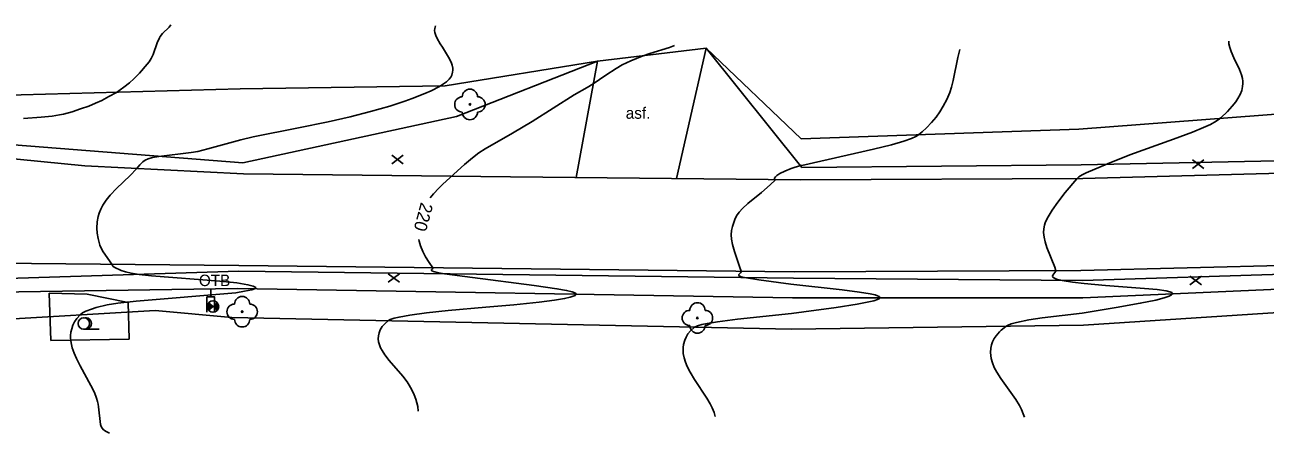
# Model space of a CAD drawing. Extents: x -593772 to -592667, y -1183541 to -1183371.
# Drawn here: x -593692.9 to -593611.5, y -1183405.1 to -1183378.3 of the extents above; entities that cross this region are included whole.
import ezdxf

# ---------------------------------------------------------------- set-up
doc = ezdxf.new("R2010")
doc.units = 0
for name, color, linetype in [('bez obruby', 7, 'Continuous'), ('hlavni vrstevnice', 7, 'Continuous'), ('popis ploch', 7, 'Continuous'), ('rozhrani ploch', 7, 'Continuous'), ('Statni bodove pole', 7, 'Continuous'), ('svisle dopravni znaceni', 7, 'Continuous'), ('terenni hrany', 7, 'Continuous'), ('vrstevnice', 7, 'Continuous'), ('zelen', 7, 'Continuous')]:
    doc.layers.add(name, color=color, linetype=linetype)

msp = doc.modelspace()

# ---------------------------------------------------------------- linework, layer by layer
at = {"layer": 'bez obruby'}
for p, q in [((-593688.93, -1183387.52), (-593695.87, -1183386.84)), ((-593678.52, -1183388.04), (-593688.93, -1183387.52)), ((-593605.56, -1183387.87), (-593623.44, -1183388.36)), ((-593660.99, -1183388.25), (-593678.52, -1183388.04)), ((-593641.96, -1183388.45), (-593660.99, -1183388.25)), ((-593623.44, -1183388.36), (-593641.96, -1183388.45)), ((-593678.82, -1183394.05), (-593694.9, -1183393.91)), ((-593642.38, -1183394.48), (-593678.82, -1183394.05)), ((-593623.56, -1183394.39), (-593642.38, -1183394.48)), ((-593605.48, -1183393.94), (-593623.56, -1183394.39))]:
    msp.add_line(p, q, dxfattribs=at)
at = {"layer": 'hlavni vrstevnice'}
for points in [[(-593650.242, -1183379.644), (-593650.564, -1183379.763), (-593651.862, -1183380.157), (-593652.355, -1183380.33), (-593653.108, -1183380.643), (-593653.661, -1183380.914), (-593654.072, -1183381.145), (-593654.742, -1183381.571), (-593655.581, -1183382.152), (-593655.956, -1183382.382), (-593656.811, -1183382.866), (-593659.585, -1183384.613), (-593660.862, -1183385.385), (-593662.658, -1183386.403), (-593663.076, -1183386.676), (-593663.493, -1183386.995), (-593664.016, -1183387.44), (-593665.438, -1183388.729), (-593665.71, -1183388.996), (-593666.058, -1183389.367), (-593666.277, -1183389.63)], [(-593667.008, -1183392.358), (-593666.988, -1183392.474), (-593666.899, -1183392.779), (-593666.753, -1183393.138), (-593666.568, -1183393.498), (-593666.345, -1183393.859), (-593666.097, -1183394.203), (-593666.09, -1183394.244), (-593666.128, -1183394.296), (-593666.183, -1183394.342), (-593666.198, -1183394.373), (-593666.171, -1183394.405), (-593666.051, -1183394.458), (-593665.733, -1183394.534), (-593665.336, -1183394.6), (-593663.482, -1183394.853), (-593659.452, -1183395.363), (-593657.951, -1183395.584), (-593657.316, -1183395.698), (-593656.943, -1183395.787), (-593656.77, -1183395.849), (-593656.701, -1183395.89), (-593656.68, -1183395.91), (-593656.675, -1183395.929), (-593656.68, -1183395.953), (-593656.747, -1183396.018), (-593656.881, -1183396.081), (-593657.073, -1183396.141), (-593657.45, -1183396.225), (-593658.11, -1183396.335), (-593659.108, -1183396.46), (-593660.779, -1183396.628), (-593662.608, -1183396.788), (-593665.08, -1183397.017), (-593666.516, -1183397.174), (-593667.594, -1183397.319), (-593668.306, -1183397.444), (-593668.636, -1183397.522), (-593668.898, -1183397.608), (-593669.011, -1183397.667), (-593669.227, -1183397.854), (-593669.411, -1183398.063), (-593669.541, -1183398.268), (-593669.624, -1183398.469), (-593669.668, -1183398.668), (-593669.676, -1183398.865), (-593669.653, -1183399.06), (-593669.601, -1183399.253), (-593669.525, -1183399.447), (-593669.427, -1183399.636), (-593669.248, -1183399.916), (-593668.961, -1183400.292), (-593668.068, -1183401.318), (-593667.778, -1183401.696), (-593667.711, -1183401.795), (-593667.49, -1183402.17), (-593667.311, -1183402.547), (-593667.204, -1183402.829), (-593667.137, -1183403.063), (-593667.088, -1183403.305), (-593667.057, -1183403.601)]]:
    msp.add_lwpolyline(points, dxfattribs=at)
at = {"layer": 'popis ploch'}
msp.add_line((-593689, -1183398.24), (-593688, -1183398.24), dxfattribs=at)
msp.add_circle((-593689, -1183397.866), 0.375, dxfattribs=at)
msp.add_arc((-593688.875, -1183397.866), 0.375, 260.40593, 99.59407, dxfattribs=at)
at = {"layer": 'rozhrani ploch'}
for p, q in [((-593655.28, -1183380.66), (-593648.15, -1183379.82)), ((-593648.15, -1183379.82), (-593650.103, -1183388.364)), ((-593656.687, -1183388.295), (-593655.28, -1183380.66))]:
    msp.add_line(p, q, dxfattribs=at)
at = {"layer": 'Statni bodove pole'}
for p, q in [((-593680.785, -1183396.485), (-593680.52, -1183396.75)), ((-593680.52, -1183396.75), (-593680.785, -1183397.015)), ((-593680.255, -1183396.485), (-593680.52, -1183396.75)), ((-593680.52, -1183396.75), (-593680.255, -1183397.015))]:
    msp.add_line(p, q, dxfattribs=at)
for points in [[(-593680.92, -1183397.12), (-593680.92, -1183396.12), (-593680.42, -1183396.12), (-593680.42, -1183397.12)], [(-593680.67, -1183396.12), (-593680.67, -1183395.62)]]:
    msp.add_lwpolyline(points, dxfattribs=at)
for radius, start, end in [(0.374, 135, 225), (0.304, 135, 225), (0.376, 45, 135), (0.234, 135, 225), (0.164, 135, 225), (0.0944, 135, 225), (0.0244, 135, 225), (0.0244, 315, 45), (0.0944, 315, 45), (0.164, 315, 45), (0.234, 315, 45), (0.304, 315, 45), (0.374, 315, 45), (0.375, 225, 315)]:
    msp.add_arc((-593680.52, -1183396.75), radius, start, end, dxfattribs=at)
at = {"layer": 'svisle dopravni znaceni'}
for p, q in [((-593668.785, -1183387.391), (-593668.035, -1183386.829)), ((-593668.785, -1183386.829), (-593668.035, -1183387.391)), ((-593616.245, -1183387.701), (-593615.495, -1183387.139)), ((-593616.245, -1183387.139), (-593615.495, -1183387.701)), ((-593669.035, -1183395.161), (-593668.285, -1183394.599)), ((-593669.035, -1183394.599), (-593668.285, -1183395.161)), ((-593616.405, -1183395.321), (-593615.655, -1183394.758)), ((-593616.405, -1183394.758), (-593615.655, -1183395.321))]:
    msp.add_line(p, q, dxfattribs=at)
at = {"layer": 'terenni hrany'}
for p, q in [((-593648.15, -1183379.82), (-593641.91, -1183385.75)), ((-593648.15, -1183379.82), (-593641.88, -1183387.64)), ((-593665.28, -1183382.28), (-593655.28, -1183380.66)), ((-593664.54, -1183384.3), (-593655.28, -1183380.66)), ((-593665.28, -1183382.28), (-593678.75, -1183382.47)), ((-593678.75, -1183382.47), (-593695.15, -1183382.93)), ((-593605.68, -1183383.75), (-593623.7, -1183385.13)), ((-593664.54, -1183384.3), (-593678.56, -1183387.34)), ((-593623.7, -1183385.13), (-593641.91, -1183385.75)), ((-593678.56, -1183387.34), (-593695.76, -1183385.98)), ((-593605.37, -1183387.08), (-593623.54, -1183387.46)), ((-593623.54, -1183387.46), (-593641.88, -1183387.64)), ((-593678.83, -1183394.43), (-593694.86, -1183394.94)), ((-593642.43, -1183394.88), (-593678.83, -1183394.43)), ((-593605.45, -1183394.48), (-593623.46, -1183395.04)), ((-593623.46, -1183395.04), (-593642.43, -1183394.88)), ((-593678.91, -1183395.57), (-593695.06, -1183395.81)), ((-593642.48, -1183396.18), (-593678.91, -1183395.57)), ((-593623.43, -1183396.17), (-593642.48, -1183396.18)), ((-593605.52, -1183395.39), (-593623.43, -1183396.17)), ((-593605.29, -1183396.79), (-593623.39, -1183397.98)), ((-593684.31, -1183397), (-593715.02, -1183398.85)), ((-593679.28, -1183397.47), (-593684.31, -1183397)), ((-593642.56, -1183398.24), (-593679.28, -1183397.47)), ((-593623.39, -1183397.98), (-593642.56, -1183398.24))]:
    msp.add_line(p, q, dxfattribs=at)
at = {"layer": 'vrstevnice'}
for points in [[(-593683.293, -1183378.282), (-593683.405, -1183378.424), (-593683.834, -1183378.854), (-593683.98, -1183379.036), (-593684.042, -1183379.144), (-593684.182, -1183379.459), (-593684.457, -1183380.23), (-593684.583, -1183380.497), (-593684.719, -1183380.712), (-593684.846, -1183380.87), (-593685.346, -1183381.443), (-593685.71, -1183381.812), (-593686.012, -1183382.084), (-593686.369, -1183382.369), (-593686.865, -1183382.708), (-593687.349, -1183382.989), (-593687.828, -1183383.234), (-593688.238, -1183383.421), (-593688.682, -1183383.605), (-593689.209, -1183383.799), (-593689.758, -1183383.975), (-593690.337, -1183384.13), (-593690.602, -1183384.189), (-593691.073, -1183384.265), (-593691.791, -1183384.34), (-593692.965, -1183384.416)], [(-593665.924, -1183378.349), (-593665.969, -1183378.525), (-593665.975, -1183378.655), (-593665.96, -1183378.786), (-593665.904, -1183378.983), (-593665.815, -1183379.187), (-593665.619, -1183379.521), (-593665.467, -1183379.75), (-593665.065, -1183380.394), (-593664.902, -1183380.723), (-593664.83, -1183380.925), (-593664.789, -1183381.121), (-593664.782, -1183381.252), (-593664.795, -1183381.383), (-593664.853, -1183381.573), (-593664.92, -1183381.703), (-593665.015, -1183381.833), (-593665.205, -1183382.017), (-593665.452, -1183382.196), (-593665.662, -1183382.32), (-593666.202, -1183382.601), (-593666.616, -1183382.789), (-593667.458, -1183383.121), (-593667.925, -1183383.288), (-593668.911, -1183383.605), (-593670.175, -1183383.968), (-593671.522, -1183384.31), (-593672.956, -1183384.636), (-593674.916, -1183385.04), (-593677.894, -1183385.631), (-593678.699, -1183385.815), (-593680.867, -1183386.422), (-593681.513, -1183386.577), (-593681.965, -1183386.655), (-593684.087, -1183386.914), (-593684.488, -1183386.987), (-593684.771, -1183387.07), (-593684.968, -1183387.161), (-593685.122, -1183387.27), (-593685.323, -1183387.462), (-593685.545, -1183387.723), (-593685.951, -1183388.158), (-593686.85, -1183389.014), (-593687.265, -1183389.455), (-593687.524, -1183389.772), (-593687.744, -1183390.096), (-593687.889, -1183390.365), (-593687.994, -1183390.625), (-593688.056, -1183390.854), (-593688.116, -1183391.203), (-593688.141, -1183391.603), (-593688.121, -1183391.945), (-593688.066, -1183392.285), (-593687.95, -1183392.727), (-593687.869, -1183392.916), (-593687.727, -1183393.156), (-593687.152, -1183393.98), (-593687.099, -1183394.096), (-593687.012, -1183394.161), (-593686.547, -1183394.377), (-593686.256, -1183394.478), (-593685.894, -1183394.567), (-593685.362, -1183394.657), (-593684.555, -1183394.745), (-593680.075, -1183395.092), (-593678.96, -1183395.204), (-593678.236, -1183395.326), (-593677.892, -1183395.413), (-593677.75, -1183395.474), (-593677.716, -1183395.513), (-593677.731, -1183395.551), (-593677.794, -1183395.587), (-593677.984, -1183395.646), (-593678.463, -1183395.753), (-593679.014, -1183395.845), (-593685.568, -1183396.407), (-593686.767, -1183396.536), (-593687.46, -1183396.645), (-593688.182, -1183396.824), (-593688.505, -1183396.923), (-593688.871, -1183397.062), (-593689.087, -1183397.168), (-593689.25, -1183397.289), (-593689.457, -1183397.536), (-593689.602, -1183397.757), (-593689.714, -1183397.98), (-593689.794, -1183398.205), (-593689.844, -1183398.43), (-593689.867, -1183398.657), (-593689.867, -1183398.773), (-593689.852, -1183399.004), (-593689.814, -1183399.235), (-593689.755, -1183399.468), (-593689.639, -1183399.813), (-593689.489, -1183400.157), (-593689.251, -1183400.629), (-593688.535, -1183401.922), (-593688.306, -1183402.394), (-593688.167, -1183402.751), (-593688.098, -1183402.983), (-593688.06, -1183403.148), (-593688.031, -1183403.325), (-593687.902, -1183404.495), (-593687.869, -1183404.625), (-593687.806, -1183404.733), (-593687.704, -1183404.833), (-593687.532, -1183404.945), (-593687.319, -1183405.052)], [(-593613.862, -1183379.363), (-593613.848, -1183379.533), (-593613.795, -1183379.777), (-593613.708, -1183380.037), (-593613.52, -1183380.456), (-593613.143, -1183381.221), (-593613.012, -1183381.56), (-593612.949, -1183381.805), (-593612.927, -1183381.971), (-593612.925, -1183382.137), (-593612.945, -1183382.316), (-593613.01, -1183382.579), (-593613.117, -1183382.847), (-593613.253, -1183383.102), (-593613.398, -1183383.323), (-593613.627, -1183383.62), (-593613.94, -1183383.964), (-593614.382, -1183384.379), (-593614.467, -1183384.45), (-593614.675, -1183384.597), (-593615.066, -1183384.812), (-593615.519, -1183385.023), (-593616.248, -1183385.324), (-593617.481, -1183385.784), (-593620.34, -1183386.809), (-593621.823, -1183387.388), (-593623.211, -1183387.985), (-593623.474, -1183388.116), (-593623.695, -1183388.251), (-593623.836, -1183388.379), (-593624.601, -1183389.28), (-593625.083, -1183389.898), (-593625.448, -1183390.424), (-593625.713, -1183390.862), (-593625.817, -1183391.057), (-593625.9, -1183391.257), (-593625.947, -1183391.408), (-593625.994, -1183391.656), (-593626.008, -1183391.905), (-593625.983, -1183392.208), (-593625.917, -1183392.514), (-593625.802, -1183392.873), (-593625.27, -1183394.164), (-593625.196, -1183394.402), (-593625.21, -1183394.437), (-593625.347, -1183394.601), (-593625.414, -1183394.699), (-593625.423, -1183394.764), (-593625.396, -1183394.818), (-593625.33, -1183394.872), (-593625.16, -1183394.946), (-593624.784, -1183395.04), (-593624.116, -1183395.151), (-593623.353, -1183395.247), (-593621.942, -1183395.365), (-593619.38, -1183395.557), (-593618.557, -1183395.639), (-593617.97, -1183395.725), (-593617.727, -1183395.782), (-593617.593, -1183395.836), (-593617.55, -1183395.873), (-593617.549, -1183395.919), (-593617.616, -1183395.986), (-593617.76, -1183396.062), (-593618.105, -1183396.183), (-593618.65, -1183396.324), (-593619.671, -1183396.537), (-593621.248, -1183396.819), (-593623.473, -1183397.175), (-593626.103, -1183397.493), (-593626.98, -1183397.628), (-593627.782, -1183397.797), (-593628.137, -1183397.894), (-593628.379, -1183397.985), (-593628.498, -1183398.052), (-593628.797, -1183398.3), (-593628.899, -1183398.399), (-593629.128, -1183398.664), (-593629.252, -1183398.853), (-593629.355, -1183399.064), (-593629.424, -1183399.269), (-593629.464, -1183399.469), (-593629.484, -1183399.762), (-593629.474, -1183399.957), (-593629.445, -1183400.156), (-593629.366, -1183400.445), (-593629.246, -1183400.737), (-593629.077, -1183401.06), (-593628.816, -1183401.471), (-593627.835, -1183402.842), (-593627.592, -1183403.236), (-593627.461, -1183403.491), (-593627.34, -1183403.783), (-593627.273, -1183404.013)], [(-593631.512, -1183379.894), (-593631.647, -1183380.427), (-593631.935, -1183381.924), (-593632.05, -1183382.363), (-593632.172, -1183382.713), (-593632.368, -1183383.17), (-593632.601, -1183383.621), (-593632.819, -1183383.982), (-593633.07, -1183384.339), (-593633.359, -1183384.694), (-593633.696, -1183385.045), (-593633.98, -1183385.305), (-593634.218, -1183385.499), (-593634.392, -1183385.607), (-593634.676, -1183385.736), (-593635.176, -1183385.913), (-593635.996, -1183386.149), (-593637.18, -1183386.443), (-593641.887, -1183387.503), (-593641.968, -1183387.51), (-593642.582, -1183387.706), (-593643.002, -1183387.87), (-593643.318, -1183388.03), (-593643.508, -1183388.158), (-593643.609, -1183388.256), (-593643.66, -1183388.338), (-593643.672, -1183388.42), (-593643.67, -1183388.429), (-593643.606, -1183388.433), (-593643.959, -1183388.781), (-593644.521, -1183389.264), (-593645.41, -1183389.996), (-593645.773, -1183390.332), (-593645.989, -1183390.568), (-593646.16, -1183390.81), (-593646.279, -1183391.052), (-593646.43, -1183391.513), (-593646.484, -1183391.755), (-593646.505, -1183392.049), (-593646.484, -1183392.344), (-593646.419, -1183392.692), (-593646.29, -1183393.14), (-593645.944, -1183394.19), (-593645.862, -1183394.44), (-593645.859, -1183394.48), (-593645.908, -1183394.546), (-593646.011, -1183394.651), (-593646.022, -1183394.698), (-593645.996, -1183394.738), (-593645.867, -1183394.801), (-593645.644, -1183394.849), (-593644.692, -1183395.004), (-593642.588, -1183395.284), (-593639.225, -1183395.651), (-593638.094, -1183395.799), (-593637.384, -1183395.918), (-593637.065, -1183395.992), (-593636.905, -1183396.042), (-593636.8, -1183396.089), (-593636.747, -1183396.134), (-593636.742, -1183396.178), (-593636.798, -1183396.236), (-593636.911, -1183396.291), (-593637.149, -1183396.368), (-593637.596, -1183396.471), (-593638.252, -1183396.594), (-593639.633, -1183396.815), (-593641.749, -1183397.105), (-593642.549, -1183397.203), (-593646.104, -1183397.581), (-593647.411, -1183397.746), (-593648.082, -1183397.854), (-593648.45, -1183397.93), (-593648.728, -1183398.012), (-593648.917, -1183398.101), (-593649.185, -1183398.341), (-593649.356, -1183398.547), (-593649.479, -1183398.751), (-593649.565, -1183398.952), (-593649.645, -1183399.248), (-593649.671, -1183399.444), (-593649.675, -1183399.639), (-593649.66, -1183399.832), (-593649.604, -1183400.118), (-593649.514, -1183400.406), (-593649.396, -1183400.686), (-593649.202, -1183401.063), (-593648.913, -1183401.536), (-593648.11, -1183402.747), (-593647.891, -1183403.122), (-593647.751, -1183403.401), (-593647.638, -1183403.688), (-593647.558, -1183403.967)]]:
    msp.add_lwpolyline(points, dxfattribs=at)
at = {"layer": 'zelen'}
for p, q in [((-593691.27, -1183395.88), (-593688.77, -1183395.93)), ((-593691.16, -1183398.98), (-593691.27, -1183395.88)), ((-593688.77, -1183395.93), (-593686.09, -1183396.49)), ((-593686.09, -1183396.49), (-593686.03, -1183398.9)), ((-593686.03, -1183398.9), (-593691.16, -1183398.98))]:
    msp.add_line(p, q, dxfattribs=at)
for centre in [(-593663.66, -1183383.5), (-593678.61, -1183397.09), (-593648.73, -1183397.5)]:
    msp.add_circle(centre, 0.05, dxfattribs=at)
for centre, start, end in [((-593664.16, -1183383.5), 90, 270), ((-593663.66, -1183383), 0, 180), ((-593663.16, -1183383.5), 270, 90), ((-593663.66, -1183384), 180, 0), ((-593678.61, -1183396.59), 0, 180), ((-593679.11, -1183397.09), 90, 270), ((-593678.11, -1183397.09), 270, 90), ((-593648.73, -1183397), 0, 180), ((-593678.61, -1183397.59), 180, 0), ((-593649.23, -1183397.5), 90, 270), ((-593648.23, -1183397.5), 270, 90), ((-593648.73, -1183398), 180, 0)]:
    msp.add_arc(centre, 0.5, start, end, dxfattribs=at)

# ---------------------------------------------------------------- texts
at = {"layer": 'hlavni vrstevnice'}
msp.add_text('220', height=0.8351, rotation=254.91046, dxfattribs=at).set_placement((-593666.873, -1183389.879))
at = {"layer": 'popis ploch'}
msp.add_text('asf.', height=0.75, dxfattribs=at).set_placement((-593653.433, -1183384.44))
at = {"layer": 'Statni bodove pole'}
msp.add_text('OTB', height=0.75, dxfattribs=at).set_placement((-593681.447, -1183395.41))

doc.saveas('drawing.dxf')
